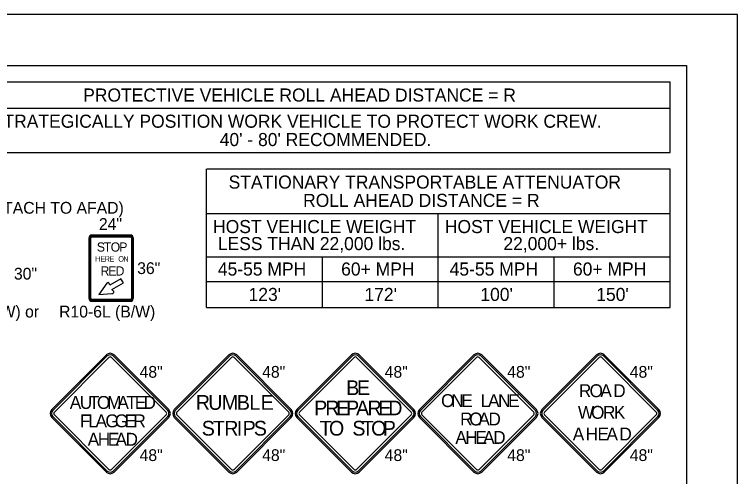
# Model space of a CAD drawing. Extents: x 99999.1 to 100095.7, y 99995 to 100010.7.
# Drawn here: x 100011.637 to 100016.062, y 100007.863 to 100010.687 of the extents above; entities that cross this region are included whole.
import ezdxf

# ---------------------------------------------------------------- set-up
doc = ezdxf.new("R2010")
doc.units = 0
for name, color, linetype in [('Default', 7, 'Continuous'), ('SH_GI_PlotLimits', 7, 'Continuous'), ('SH_GI_SheetBorder', 7, 'Continuous'), ('SH_TI_Tables', 7, 'Continuous'), ('TR_SN_ConstructionSigns', 7, 'Continuous'), ('TR_WZ_WorkZoneDetails', 7, 'Continuous')]:
    doc.layers.add(name, color=color, linetype=linetype)

msp = doc.modelspace()

# ---------------------------------------------------------------- linework, layer by layer
at = {"layer": 'Default'}
for p, q in [((100012.9495, 100008.6062), (100012.6154, 100008.2721)), ((100013.3313, 100008.2721), (100012.9972, 100008.6062)), ((100012.6154, 100008.2243), (100012.9495, 100007.8902)), ((100012.9972, 100007.8902), (100013.3313, 100008.2243))]:
    msp.add_line(p, q, dxfattribs=at)
for centre, start, end in [((100012.9733, 100008.5823), 45, 135), ((100012.6392, 100008.2482), 135, 225), ((100013.3075, 100008.2482), 315, 45), ((100012.9733, 100007.9141), 225, 315)]:
    msp.add_arc(centre, 0.0338, start, end, dxfattribs=at)
at = {"layer": 'SH_GI_PlotLimits'}
msp.add_lwpolyline([(99999.0625, 99999.6875), (100016.0625, 99999.6875), (100016.0625, 100010.6875), (99999.0625, 100010.6875)], close=True, dxfattribs=at)
at = {"layer": 'SH_GI_SheetBorder'}
for p, q in [((100000, 100010.375), (100015.75, 100010.375)), ((100015.75, 100010.375), (100015.75, 100000))]:
    msp.add_line(p, q, dxfattribs=at)
at = {"layer": 'SH_TI_Tables'}
for p, q in [((100011.4347, 100010.275), (100015.65, 100010.275)), ((100015.65, 100009.843), (100015.65, 100010.275)), ((100011.4347, 100010.115), (100015.65, 100010.115)), ((100011.4347, 100009.843), (100015.65, 100009.843)), ((100012.8126, 100008.896), (100012.8126, 100009.743)), ((100012.8156, 100009.743), (100015.65, 100009.743)), ((100015.65, 100008.896), (100015.65, 100009.743)), ((100012.8126, 100009.471), (100015.65, 100009.471)), ((100014.2313, 100008.896), (100014.2313, 100009.471)), ((100012.8126, 100009.2069), (100014.2313, 100009.2069)), ((100013.5219, 100008.896), (100013.5219, 100009.2069)), ((100014.2313, 100009.2069), (100015.65, 100009.2069)), ((100014.9406, 100008.896), (100014.9406, 100009.2069)), ((100012.8126, 100009.056), (100014.2313, 100009.056)), ((100014.2313, 100009.056), (100015.65, 100009.056)), ((100012.8126, 100008.896), (100015.65, 100008.896))]:
    msp.add_line(p, q, dxfattribs=at)
at = {"layer": 'TR_SN_ConstructionSigns'}
for p, q in [((100012.0939, 100009.3222), (100012.0939, 100008.951)), ((100012.0939, 100008.951), (100012.0939, 100009.3222)), ((100012.0939, 100009.3222), (100012.0939, 100008.951)), ((100012.0981, 100009.3222), (100012.0981, 100008.951)), ((100012.1052, 100008.951), (100012.1052, 100009.3222)), ((100012.347, 100009.3391), (100012.1108, 100009.3391)), ((100012.1108, 100009.3391), (100012.347, 100009.3391)), ((100012.347, 100009.3391), (100012.1108, 100009.3391)), ((100012.347, 100009.3349), (100012.1108, 100009.3349)), ((100012.1108, 100009.3279), (100012.347, 100009.3279)), ((100012.3527, 100009.3222), (100012.3527, 100008.951)), ((100012.3597, 100008.951), (100012.3597, 100009.3222)), ((100012.3639, 100008.951), (100012.3639, 100009.3222)), ((100012.3639, 100009.3222), (100012.3639, 100008.951)), ((100012.3639, 100008.951), (100012.3639, 100009.3222)), ((100012.289, 100009.0719), (100012.22, 100009.0321)), ((100012.3037, 100009.0463), (100012.289, 100009.0719)), ((100012.2015, 100009.0445), (100012.1541, 100008.9764)), ((100012.22, 100009.0321), (100012.2166, 100009.0435)), ((100012.234, 100009.0061), (100012.3037, 100009.0463)), ((100012.2451, 100008.9938), (100012.234, 100009.0061)), ((100012.1541, 100008.9764), (100012.2332, 100008.9819)), ((100012.347, 100008.9454), (100012.1108, 100008.9454)), ((100012.1108, 100008.9383), (100012.347, 100008.9383)), ((100012.1108, 100008.9341), (100012.347, 100008.9341)), ((100012.347, 100008.9341), (100012.1108, 100008.9341)), ((100012.1108, 100008.9341), (100012.347, 100008.9341)), ((100012.1995, 100008.6062), (100011.8654, 100008.2721)), ((100012.5813, 100008.2721), (100012.2472, 100008.6062)), ((100012.6154, 100008.2721), (100012.9495, 100008.6062)), ((100012.9972, 100008.6062), (100013.3313, 100008.2721)), ((100013.3654, 100008.2721), (100013.6995, 100008.6062)), ((100013.7472, 100008.6062), (100014.0813, 100008.2721)), ((100014.1154, 100008.2721), (100014.4495, 100008.6062)), ((100014.4972, 100008.6062), (100014.8313, 100008.2721)), ((100014.8654, 100008.2721), (100015.1995, 100008.6062)), ((100015.2472, 100008.6062), (100015.5813, 100008.2721)), ((100012.2055, 100008.6002), (100011.8713, 100008.2661)), ((100011.8813, 100008.2561), (100012.2154, 100008.5903)), ((100012.2313, 100008.5903), (100012.5654, 100008.2561)), ((100012.5754, 100008.2661), (100012.2412, 100008.6002)), ((100012.9555, 100008.6002), (100012.6213, 100008.2661)), ((100012.6313, 100008.2561), (100012.9654, 100008.5903)), ((100012.9813, 100008.5903), (100013.3154, 100008.2561)), ((100013.3254, 100008.2661), (100012.9912, 100008.6002)), ((100013.7055, 100008.6002), (100013.3713, 100008.2661)), ((100013.3813, 100008.2561), (100013.7154, 100008.5903)), ((100013.7313, 100008.5903), (100014.0654, 100008.2561)), ((100014.0754, 100008.2661), (100013.7412, 100008.6002)), ((100014.4555, 100008.6002), (100014.1213, 100008.2661)), ((100014.1313, 100008.2561), (100014.4654, 100008.5903)), ((100014.4813, 100008.5903), (100014.8154, 100008.2561)), ((100014.8254, 100008.2661), (100014.4912, 100008.6002)), ((100015.2055, 100008.6002), (100014.8713, 100008.2661)), ((100014.8813, 100008.2561), (100015.2154, 100008.5903)), ((100015.2313, 100008.5903), (100015.5654, 100008.2561)), ((100015.5754, 100008.2661), (100015.2412, 100008.6002)), ((100011.8654, 100008.2243), (100012.1995, 100007.8902)), ((100011.8713, 100008.2303), (100012.2055, 100007.8962)), ((100012.2154, 100007.9061), (100011.8813, 100008.2402)), ((100012.5654, 100008.2402), (100012.2313, 100007.9061)), ((100012.2412, 100007.8962), (100012.5754, 100008.2303)), ((100012.2472, 100007.8902), (100012.5813, 100008.2243)), ((100012.9495, 100007.8902), (100012.6154, 100008.2243)), ((100012.6213, 100008.2303), (100012.9555, 100007.8962)), ((100012.9654, 100007.9061), (100012.6313, 100008.2402)), ((100013.3154, 100008.2402), (100012.9813, 100007.9061)), ((100012.9912, 100007.8962), (100013.3254, 100008.2303)), ((100013.3313, 100008.2243), (100012.9972, 100007.8902)), ((100013.6995, 100007.8902), (100013.3654, 100008.2243)), ((100013.3713, 100008.2303), (100013.7055, 100007.8962)), ((100013.7154, 100007.9061), (100013.3813, 100008.2402)), ((100014.0654, 100008.2402), (100013.7313, 100007.9061)), ((100013.7412, 100007.8962), (100014.0754, 100008.2303)), ((100014.0813, 100008.2243), (100013.7472, 100007.8902)), ((100014.4495, 100007.8902), (100014.1154, 100008.2243)), ((100014.1213, 100008.2303), (100014.4555, 100007.8962)), ((100014.4654, 100007.9061), (100014.1313, 100008.2402)), ((100014.8154, 100008.2402), (100014.4813, 100007.9061)), ((100014.4912, 100007.8962), (100014.8254, 100008.2303)), ((100014.8313, 100008.2243), (100014.4972, 100007.8902)), ((100015.1995, 100007.8902), (100014.8654, 100008.2243)), ((100014.8713, 100008.2303), (100015.2055, 100007.8962)), ((100015.2154, 100007.9061), (100014.8813, 100008.2402)), ((100015.5654, 100008.2402), (100015.2313, 100007.9061)), ((100015.2412, 100007.8962), (100015.5754, 100008.2303)), ((100015.5813, 100008.2243), (100015.2472, 100007.8902))]:
    msp.add_line(p, q, dxfattribs=at)
for centre, radius, start, end in [((100012.1108, 100009.3222), 0.0169, 90, 180), ((100012.1108, 100009.3222), 0.0169, 90, 180), ((100012.1108, 100009.3222), 0.0169, 90, 180), ((100012.1108, 100009.3222), 0.0127, 90, 180), ((100012.1108, 100009.3222), 0.00562, 90, 180), ((100012.347, 100009.3222), 0.0169, 0, 90), ((100012.347, 100009.3222), 0.0169, 0, 90), ((100012.347, 100009.3222), 0.0169, 0, 90), ((100012.347, 100009.3222), 0.0127, 0, 90), ((100012.347, 100009.3222), 0.00562, 0, 90), ((100012.1108, 100008.951), 0.0169, 180, 270), ((100012.1108, 100008.951), 0.0169, 180, 270), ((100012.1108, 100008.951), 0.0169, 180, 270), ((100012.1108, 100008.951), 0.0127, 180, 270), ((100012.1108, 100008.951), 0.00562, 180, 270), ((100012.347, 100008.951), 0.0169, 270, 0), ((100012.347, 100008.951), 0.0169, 270, 0), ((100012.347, 100008.951), 0.0169, 270, 0), ((100012.347, 100008.951), 0.0127, 270, 0), ((100012.347, 100008.951), 0.00562, 270, 0), ((100012.2233, 100008.5823), 0.0338, 45, 135), ((100012.2233, 100008.5823), 0.0253, 45, 135), ((100012.9733, 100008.5823), 0.0338, 45, 135), ((100012.9733, 100008.5823), 0.0253, 45, 135), ((100013.7233, 100008.5823), 0.0338, 45, 135), ((100013.7233, 100008.5823), 0.0253, 45, 135), ((100014.4733, 100008.5823), 0.0338, 45, 135), ((100014.4733, 100008.5823), 0.0253, 45, 135), ((100015.2233, 100008.5823), 0.0338, 45, 135), ((100015.2233, 100008.5823), 0.0253, 45, 135), ((100012.2233, 100008.5823), 0.0113, 45, 135), ((100012.9733, 100008.5823), 0.0113, 45, 135), ((100013.7233, 100008.5823), 0.0113, 45, 135), ((100014.4733, 100008.5823), 0.0113, 45, 135), ((100015.2233, 100008.5823), 0.0113, 45, 135), ((100011.8892, 100008.2482), 0.0338, 135, 225), ((100011.8892, 100008.2482), 0.0253, 135, 225), ((100011.8892, 100008.2482), 0.0113, 135, 225), ((100012.5575, 100008.2482), 0.0113, 315, 45), ((100012.5575, 100008.2482), 0.0253, 315, 45), ((100012.5575, 100008.2482), 0.0338, 315, 45), ((100012.6392, 100008.2482), 0.0338, 135, 225), ((100012.6392, 100008.2482), 0.0253, 135, 225), ((100012.6392, 100008.2482), 0.0113, 135, 225), ((100013.3075, 100008.2482), 0.0113, 315, 45), ((100013.3075, 100008.2482), 0.0253, 315, 45), ((100013.3075, 100008.2482), 0.0338, 315, 45), ((100013.3892, 100008.2482), 0.0338, 135, 225), ((100013.3892, 100008.2482), 0.0253, 135, 225), ((100013.3892, 100008.2482), 0.0113, 135, 225), ((100014.0575, 100008.2482), 0.0113, 315, 45), ((100014.0575, 100008.2482), 0.0253, 315, 45), ((100014.0575, 100008.2482), 0.0338, 315, 45), ((100014.1392, 100008.2482), 0.0338, 135, 225), ((100014.1392, 100008.2482), 0.0253, 135, 225), ((100014.1392, 100008.2482), 0.0113, 135, 225), ((100014.8075, 100008.2482), 0.0113, 315, 45), ((100014.8075, 100008.2482), 0.0253, 315, 45), ((100014.8075, 100008.2482), 0.0338, 315, 45), ((100014.8892, 100008.2482), 0.0338, 135, 225), ((100014.8892, 100008.2482), 0.0253, 135, 225), ((100014.8892, 100008.2482), 0.0113, 135, 225), ((100015.5575, 100008.2482), 0.0113, 315, 45), ((100015.5575, 100008.2482), 0.0253, 315, 45), ((100015.5575, 100008.2482), 0.0338, 315, 45), ((100012.2233, 100007.9141), 0.0113, 225, 315), ((100012.9733, 100007.9141), 0.0113, 225, 315), ((100013.7233, 100007.9141), 0.0113, 225, 315), ((100014.4733, 100007.9141), 0.0113, 225, 315), ((100015.2233, 100007.9141), 0.0113, 225, 315), ((100012.2233, 100007.9141), 0.0338, 225, 315), ((100012.2233, 100007.9141), 0.0253, 225, 315), ((100012.9733, 100007.9141), 0.0338, 225, 315), ((100012.9733, 100007.9141), 0.0253, 225, 315), ((100013.7233, 100007.9141), 0.0338, 225, 315), ((100013.7233, 100007.9141), 0.0253, 225, 315), ((100014.4733, 100007.9141), 0.0338, 225, 315), ((100014.4733, 100007.9141), 0.0253, 225, 315), ((100015.2233, 100007.9141), 0.0338, 225, 315), ((100015.2233, 100007.9141), 0.0253, 225, 315)]:
    msp.add_arc(centre, radius, start, end, dxfattribs=at)
for centre, major_axis, start_param, end_param in [((100012.2076, 100009.0406), (0.00841, 0.00485), 5.977036, 8.198856), ((100012.2368, 100008.9893), (-0.00822, -0.00474), 0.771965, 3.092601)]:
    msp.add_ellipse(centre, major_axis=major_axis, ratio=0.700347, start_param=start_param, end_param=end_param, dxfattribs=at)
at = {"layer": 'TR_WZ_WorkZoneDetails'}
for p, q in [((100013.6995, 100008.6062), (100013.3654, 100008.2721)), ((100014.0813, 100008.2721), (100013.7472, 100008.6062)), ((100014.4495, 100008.6062), (100014.1154, 100008.2721)), ((100014.8313, 100008.2721), (100014.4972, 100008.6062)), ((100015.1995, 100008.6062), (100014.8654, 100008.2721)), ((100015.5813, 100008.2721), (100015.2472, 100008.6062)), ((100013.3654, 100008.2243), (100013.6995, 100007.8902)), ((100013.7472, 100007.8902), (100014.0813, 100008.2243)), ((100014.1154, 100008.2243), (100014.4495, 100007.8902)), ((100014.4972, 100007.8902), (100014.8313, 100008.2243)), ((100014.8654, 100008.2243), (100015.1995, 100007.8902)), ((100015.2472, 100007.8902), (100015.5813, 100008.2243))]:
    msp.add_line(p, q, dxfattribs=at)
for centre, start, end in [((100013.7233, 100008.5823), 45, 135), ((100014.4733, 100008.5823), 45, 135), ((100015.2233, 100008.5823), 45, 135), ((100013.3892, 100008.2482), 135, 225), ((100014.0575, 100008.2482), 315, 45), ((100014.1392, 100008.2482), 135, 225), ((100014.8075, 100008.2482), 315, 45), ((100014.8892, 100008.2482), 135, 225), ((100015.5575, 100008.2482), 315, 45), ((100013.7233, 100007.9141), 225, 315), ((100014.4733, 100007.9141), 225, 315), ((100015.2233, 100007.9141), 225, 315)]:
    msp.add_arc(centre, 0.0338, start, end, dxfattribs=at)

# ---------------------------------------------------------------- texts
at = {"layer": 'Default'}
for s, p in [('R', (100012.747, 100008.2707)), ('U', (100012.8235, 100008.2707)), ('M', (100012.9063, 100008.2707)), ('B', (100012.9981, 100008.2707)), ('L', (100013.0746, 100008.2707)), ('E', (100013.1439, 100008.2707)), ('S', (100012.7834, 100008.1132)), ('T', (100012.8518, 100008.1132)), ('R', (100012.9211, 100008.1132)), ('I', (100012.9976, 100008.1132)), ('P', (100013.0336, 100008.1132)), ('S', (100013.102, 100008.1132))]:
    msp.add_text(s, height=0.09, dxfattribs=at).set_placement(p)
at = {"layer": 'SH_TI_Tables'}
for s, p in [('PROTECTIVE VEHICLE ROLL AHEAD DISTANCE = R', (100012.0577, 100010.155)), ('STRATEGICALLY POSITION WORK VEHICLE TO PROTECT WORK CREW.', (100011.4984, 100009.995)), ("40' - 80'", (100012.8935, 100009.883)), ('RECOMMENDED.', (100013.297, 100009.883)), ('STATIONARY TRANSPORTABLE ATTENUATOR', (100012.9479, 100009.623)), ('ROLL AHEAD DISTANCE = R', (100013.4035, 100009.511)), ('HOST VEHICLE WEIGHT', (100012.8526, 100009.351)), ('HOST VEHICLE WEIGHT', (100014.2713, 100009.351)), ('LESS THAN 22,000 lbs.', (100012.8817, 100009.2469)), ('22,000+ lbs.', (100014.6295, 100009.2469)), ('45-55 MPH', (100012.8818, 100009.0914)), ('60+ MPH', (100013.6365, 100009.0914)), ('45-55 MPH', (100014.3006, 100009.0914)), ('60+ MPH', (100015.0552, 100009.0914)), ("123'", (100013.0698, 100008.936)), ("172'", (100013.7792, 100008.936)), ("100'", (100014.4885, 100008.936)), ("150'", (100015.1979, 100008.936))]:
    msp.add_text(s, height=0.08, rotation=360, dxfattribs=at).set_placement(p)
at = {"layer": 'TR_SN_ConstructionSigns'}
for s, p in [('(MAY ATTACH TO AFAD)', (100011.1775, 100009.4696)), ('24"', (100012.1539, 100009.3706)), ('30"', (100011.634, 100009.0669)), ('36"', (100012.3882, 100009.1006)), ('R10-6A (B/W) or', (100011.0761, 100008.8351)), ('R10-6L (B/W)', (100011.9104, 100008.8351)), ('48"', (100012.4031, 100008.4667)), ('48"', (100013.1531, 100008.4667)), ('48"', (100013.9031, 100008.4667)), ('48"', (100014.6531, 100008.4667)), ('48"', (100015.4031, 100008.4667)), ('48"', (100012.4031, 100007.9576)), ('48"', (100013.1531, 100007.9576)), ('48"', (100013.9031, 100007.9576)), ('48"', (100014.6531, 100007.9576)), ('48"', (100015.4031, 100007.9576))]:
    msp.add_text(s, height=0.072, rotation=360, dxfattribs=at).set_placement(p)
for s, height, p in [('S', 0.0562, (100012.1412, 100009.2379)), ('T', 0.0562, (100012.1839, 100009.2379)), ('O', 0.0562, (100012.2261, 100009.2379)), ('P', 0.0562, (100012.2784, 100009.2379)), ('H', 0.0338, (100012.1312, 100009.176)), ('E', 0.0338, (100012.1623, 100009.176)), ('R', 0.0338, (100012.1889, 100009.176)), ('E', 0.0338, (100012.2176, 100009.176)), ('O', 0.0338, (100012.2723, 100009.176)), ('N', 0.0338, (100012.3037, 100009.176)), ('R', 0.0562, (100012.1637, 100009.0916)), ('E', 0.0562, (100012.2115, 100009.0916)), ('D', 0.0562, (100012.2559, 100009.0916)), ('A', 0.0787, (100011.9757, 100008.2763)), ('U', 0.0787, (100012.0371, 100008.2763)), ('T', 0.0787, (100012.0922, 100008.2763)), ('O', 0.0787, (100012.1418, 100008.2763)), ('M', 0.0787, (100012.2041, 100008.2763)), ('A', 0.0787, (100012.2671, 100008.2763)), ('T', 0.0787, (100012.3222, 100008.2763)), ('E', 0.0787, (100012.3734, 100008.2763)), ('D', 0.0787, (100012.4269, 100008.2763)), ('F', 0.0787, (100012.0375, 100008.1638)), ('L', 0.0787, (100012.0887, 100008.1638)), ('A', 0.0787, (100012.1336, 100008.1638)), ('G', 0.0787, (100012.1934, 100008.1638)), ('G', 0.0787, (100012.2517, 100008.1638)), ('E', 0.0787, (100012.3115, 100008.1638)), ('R', 0.0787, (100012.3651, 100008.1638)), ('A', 0.0787, (100012.0855, 100008.0513)), ('H', 0.0787, (100012.147, 100008.0513)), ('E', 0.0787, (100012.2084, 100008.0513)), ('A', 0.0787, (100012.2556, 100008.0513)), ('D', 0.0787, (100012.3171, 100008.0513))]:
    msp.add_text(s, height=height, dxfattribs=at).set_placement(p)
at = {"layer": 'TR_WZ_WorkZoneDetails'}
for s, height, p in [('B', 0.09, (100013.6675, 100008.3607)), ('E', 0.09, (100013.7332, 100008.3607)), ('R', 0.0788, (100015.0914, 100008.348)), ('O', 0.0788, (100015.1568, 100008.348)), ('A', 0.0788, (100015.223, 100008.348)), ('D', 0.0788, (100015.3017, 100008.348)), ('O', 0.0787, (100014.2481, 100008.2876)), ('N', 0.0787, (100014.3103, 100008.2876)), ('E', 0.0787, (100014.3718, 100008.2876)), ('L', 0.0787, (100014.4907, 100008.2876)), ('A', 0.0787, (100014.5356, 100008.2876)), ('N', 0.0787, (100014.597, 100008.2876)), ('E', 0.0787, (100014.6584, 100008.2876)), ('P', 0.09, (100013.4713, 100008.2369)), ('R', 0.09, (100013.5397, 100008.2369)), ('E', 0.09, (100013.6054, 100008.2369)), ('P', 0.09, (100013.6666, 100008.2369)), ('A', 0.09, (100013.7278, 100008.2369)), ('R', 0.09, (100013.798, 100008.2369)), ('E', 0.09, (100013.8637, 100008.2369)), ('D', 0.09, (100013.9249, 100008.2369)), ('R', 0.0787, (100014.3647, 100008.1751)), ('O', 0.0787, (100014.4206, 100008.1751)), ('A', 0.0787, (100014.4765, 100008.1751)), ('D', 0.0787, (100014.5379, 100008.1751)), ('W', 0.0788, (100015.0855, 100008.2158)), ('O', 0.0788, (100015.1659, 100008.2158)), ('R', 0.0788, (100015.2391, 100008.2158)), ('K', 0.0788, (100015.306, 100008.2158)), ('T', 0.09, (100013.5051, 100008.1132)), ('O', 0.09, (100013.5618, 100008.1132)), ('S', 0.09, (100013.7049, 100008.1132)), ('T', 0.09, (100013.7634, 100008.1132)), ('O', 0.09, (100013.8201, 100008.1132)), ('P', 0.09, (100013.8912, 100008.1132)), ('A', 0.0787, (100014.3355, 100008.0626)), ('H', 0.0787, (100014.397, 100008.0626)), ('E', 0.0787, (100014.4584, 100008.0626)), ('A', 0.0787, (100014.5056, 100008.0626)), ('D', 0.0787, (100014.5671, 100008.0626)), ('A', 0.0788, (100015.054, 100008.0837)), ('H', 0.0788, (100015.1328, 100008.0837)), ('E', 0.0788, (100015.2052, 100008.0837)), ('A', 0.0788, (100015.2604, 100008.0837)), ('D', 0.0788, (100015.3391, 100008.0837))]:
    msp.add_text(s, height=height, dxfattribs=at).set_placement(p)

doc.saveas('drawing.dxf')
